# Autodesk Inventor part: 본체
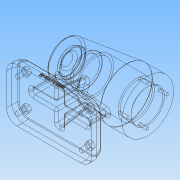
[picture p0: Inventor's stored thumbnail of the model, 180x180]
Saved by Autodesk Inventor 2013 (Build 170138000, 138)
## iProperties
Created: 2017-01
Part Number: 본체
Material: 일반
Document SubType Name: Modeling
Designer: Administrator
Density: 1 g/cm^3
Author: Administrator
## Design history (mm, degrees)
sketch "스케치1"
  geometry: L1 (28, 34)-(-52.27, 24.144); L2 (28, 34)-(56, 34); L3 (56, 34)-(56, 0); L4 (56, 0)-(-56, 0); A1 r 80 centre (24, 0) between (-52.27, 24.144) and (-56, 0); 2 further points
  constraints: 8 end point, 2 point on circle, 2 point on line, 1 centre point, 1 coincident, 1 horizontal, 1 midpoint, 1 parallel, 1 perpendicular
  dimensions: "d0" = 7 deg angle of L2 L1; "d1" = 28 distance of L1.start L2.end; "d3" = 112 distance from line of A1.end L3; "d4" = 80 radius of A1; "d5" = 68 diameter of L2 L4; "d6" = 56 distance of A1.end point (0, 0)
revolve "회전1" sketch "스케치1" stored, may be unused: angle "d7" = 90 deg
node "작업 평면1"
sketch "스케치2"
  geometry: L1 (56, -35)-(-56, -35); L2 (-56, -35)-(-56, 35); L3 (-56, 35)-(56, 35); L4 (56, 35)-(56, -35); 1 further point
  constraints: 8 end point, 2 parallel, 1 horizontal, 1 perpendicular
  dimensions: "d9" = 56 distance from line of L2 point (0, 0); "d10" = 112 distance between parallel lines of L4 L2; "d11" = 70 distance of L1.end L2.end; "d12" = 35 distance from line of L1 point (0, 0)
extrude "돌출1" join sketch "스케치2" distance "d13" = 7; taper "d14" = 0 deg
sketch "스케치3"
  geometry: L1 (-56, -67)-(56, -67) reference; L2 (-56, -67)-(-54.124, -60); L3 (-54.124, -60)-(54.124, -60); L4 (54.124, -60)-(56, -67); L5 (-56, -74)-(-56, -67) reference; L6 (56, -74)-(56, -67) reference; 1 further point
  constraints: 6 end point, 1 parallel
  dimensions: "d15" = 15 deg angle of L5 L2; "d16" = 15 deg angle of L6 L4; "d17" = 7 distance between parallel lines of L3 L1
extrude "돌출2" join sketch "스케치3" stored distance "d18" = 70; taper "d19" = 0 deg
sketch "스케치4"
  geometry: L1 (70, 0)-(70, 7) reference; L2 (0, 7)-(70, 7) reference; L3 (0, 0)-(0, 7) reference; L4 (0, 7)-(1.876, 14); L5 (1.876, 14)-(68.124, 14); L6 (68.124, 14)-(70, 7); L7 (0, 14)-(70, 14) reference; L8 (70, 7)-(0, 7); L9 (1.876, 14)-(0, 14); L10 (0, 14)-(0, 7); L11 (70, 7)-(70, 14); L12 (70, 14)-(68.124, 14); 1 further point
  constraints: 16 end point, 2 equal length, 1 perpendicular
  dimensions: "d20" = 15 deg angle of L1 L6; "d21" = 15 deg angle of L3 L4; "d23" = 7 distance between parallel lines of L2 L5
extrude "돌출3" cut sketch "스케치4" stored distance "d24" = 70; taper "d25" = 0 deg
sketch "스케치5"
  geometry: L1 (50.124, 49.767)-(58.124, 49.767); L2 (58.124, 49.767)-(58.124, 11.361); L3 (58.124, 11.361)-(50.124, 11.361); L4 (50.124, 11.361)-(50.124, 49.767); L5 (16.124, 37.124)-(92.124, 37.124); L6 (92.124, 37.124)-(92.124, 29.124); L7 (92.124, 29.124)-(16.124, 29.124); L8 (16.124, 29.124)-(16.124, 37.124); L9 (-1.876, 68.124)-(-1.876, -1.876) reference; L10 (110.124, -1.876)-(110.124, 68.124) reference; 1 further point
  constraints: 16 end point, 4 parallel, 2 horizontal, 2 perpendicular
  dimensions: "d27" = 4 distance from line of L5 point (54.124, 33.124); "d28" = 8 distance between parallel lines of L7 L5; "d29" = 4 distance from line of L4 point (54.124, 33.124); "d30" = 8 distance between parallel lines of L2 L4; "d31" = 18 distance between parallel lines of L9 L8; "d32" = 18 distance between parallel lines of L10 L6
extrude "돌출4" join sketch "스케치5" stored distance "d33" = 70; taper "d34" = 0 deg
sketch "스케치6"
  geometry: L1 (-26.866, 17.158)-(-60, 23); L2 (-60, -33.124)-(-60, 33.124) reference; L3 (-74, 35)-(-67, 35) reference; 1 further point
  constraints: 2 end point, 1 point on line
  dimensions: "d35" = 100 deg angle of L2 L1; "d36" = 12 distance from line of L1.end L3
feature "리브1" sketch "스케치6" dims "d37" = 1, "d38" = 8, "d39" = 0, "d40" = 0, "d41" = 1, "d42" = 1
sketch "스케치7"
  geometry: L1 (56, -34)-(56, 34) reference; L2 (28, 34)-(56, 34) reference; L3 (-52.27, 24.144)-(28, 34) reference; L4 (41, 0)-(56, 0); L5 (56, 0)-(56, 21); L6 (56, 21)-(41, 21); L7 (41, 21)-(41, 0); L8 (41, 0)-(-13, 0); L9 (-13, 0)-(-13, 24); L10 (-13, 24)-(41, 24); L11 (41, 24)-(41, 0); L12 (-13, 0)-(-25, 0); L13 (-25, 0)-(-25, 21); L14 (-25, 21)-(-13, 21); L15 (-13, 21)-(-13, 0); L16 (-25, 0)-(-43, 0); L17 (-43, 0)-(-43, 17.5); L18 (-43, 17.5)-(-25, 17.5); L19 (-25, 17.5)-(-25, 0); L20 (-43, 0)-(-47, 0); L21 (-47, 0)-(-47, 16); L22 (-47, 16)-(-43, 16); L23 (-43, 16)-(-43, 0); L24 (-47, 0)-(-50, 0); L25 (-50, 0)-(-50, 10.5); L26 (-50, 10.5)-(-47, 10.5); L27 (-47, 10.5)-(-47, 0); A1 r 80 centre (24, 0) between (-52.27, 24.144) and (-52.27, -24.144) reference; 2 further points
  constraints: 48 end point, 12 parallel, 6 horizontal, 6 perpendicular, 3 point on line, 1 midpoint
  dimensions: "d50" = 15 distance between parallel lines of L7 L1; "d51" = 54 distance between parallel lines of L15 L7; "d52" = 42 diameter of L6 L4; "d54" = 48 diameter of L10 L8; "d55" = 12 distance between parallel lines of L19 L15; "d57" = 35 diameter of L18 L16; "d58" = 42 diameter of L14 L12; "d59" = 32 diameter of L22 L20; "d60" = 18 distance between parallel lines of L13 L17; "d61" = 4 distance between parallel lines of L21 L17; "d62" = 3 distance between parallel lines of L25 L21; "d63" = 21 diameter of L26 L24
revolve "회전2" sketch "스케치7" stored, may be unused: angle "d64" = 90 deg
fillet "모깎기1" dims "d65" = 3
sketch "스케치8"
  geometry: C1 r 21 at (0, 0) reference; 1 further point
  constraints: 1 vertical alignment
  dimensions: "d66" = 26 distance of C1.centre point (0, 26)
hole "구멍1" sketch "스케치8" at (0, 26) diameter "d67" = 3.242; stored, may be unused: countersink angle "d71" = 90 deg, drill point angle "d73" = 118 deg; dims "d68" = 8, "d69" = 4, "d70" = 2, "d72" = 11
fillet "모깎기2" dims "d77" = 0.3
fillet "모깎기4" dims "d79" = 14
fillet "모깎기5" dims "d80" = 14
sketch "스케치9" dims "d82" = 5
  geometry: L1 (81.203, 66.249)-(0, 66.249) reference; L2 (-1.399, 68.124)-(82.601, 68.124) reference; L3 (-15.399, 54.124)-(-15.399, 12.124) reference; L4 (40.601, 33.124)-(40.601, 49.124); L5 (77.733, 55.262)-(79.181, 50.477); L6 (79.181, 50.477)-(84.05, 49.339); L7 (86.021, 57.772)-(81.153, 58.91); L8 (87.47, 52.986)-(86.021, 57.772); L9 (84.05, 49.339)-(87.47, 52.986); L10 (81.153, 58.91)-(77.733, 55.262); L11 (1.101, 58.454)-(3.601, 54.124); L12 (3.601, 54.124)-(1.101, 49.794); L13 (1.101, 49.794)-(-3.899, 49.794); L14 (-3.899, 49.794)-(-6.399, 54.124); L15 (-6.399, 54.124)-(-3.899, 58.454); L16 (-3.899, 58.454)-(1.101, 58.454); 8 further points; 1 other entity
  constraints: 26 end point, 3 coincident, 3 symmetric about line, 2 parallel, 1 vertical, 20 other
  dimensions: "d84" = 14 distance from line of L2 point (-1.399, 54.124); "d85" = 14 distance from line of L3 point (-1.399, 54.124)
extrude "돌출5" cut sketch "스케치9" distance "d86" = 4; taper "d87" = 0 deg
sketch "스케치10"
  geometry: L1 (1.101, 49.794)-(-3.899, 49.794) reference; L2 (3.601, 54.124)-(-6.399, 54.124); C1 r 2.5 at (-1.399, 54.124); 1 further point
  constraints: 2 end point, 1 centre point, 1 midpoint, 1 parallel
  dimensions: "d88" = 2.5 radius of C1
extrude "돌출6" cut sketch "스케치10" stored distance "d89" = 4; taper "d90" = 0 deg
fillet "모깎기6" dims "d91" = 3
fillet "모깎기7" dims "d92" = 3
node "작업 평면2"
sketch "스케치11"
  geometry: L1 (42, -74)-(-42, -74) reference; L2 (56, -74)-(56, -67) reference; 2 further points
  constraints: 1 other
  dimensions: "d95" = 4 distance from line of L1 point (0, -70); "d96" = 56 distance from line of L2 point (0, -70)
feature "엠보싱1" sketch "스케치11" dims "d0" = 7 deg, "d1" = 28, "d3" = 112, "d4" = 80, "d5" = 68, "d6" = 56, "d15" = 15 deg, "d16" = 15 deg, "d17" = 7, "d97" = 0.5, "d98" = 0
chamfer "모따기1" distance "d99" = 1; stored, may be unused: second distance "d100" = 2, angle "d101" = 45 deg
fillet "모깎기9" dims "d102" = 1
fillet "모깎기10" dims "d103" = 3
fillet "모깎기11" dims "d104" = 3
fillet "모깎기12" dims "d105" = 3
node "솔리드1"
mirror "대칭1"
pattern_circular "원형 패턴1" dims angle "d75" = 360 deg
mirror "대칭2"
mirror "대칭3"
other parameters: "d8" = -74, "d94" = 70.5
